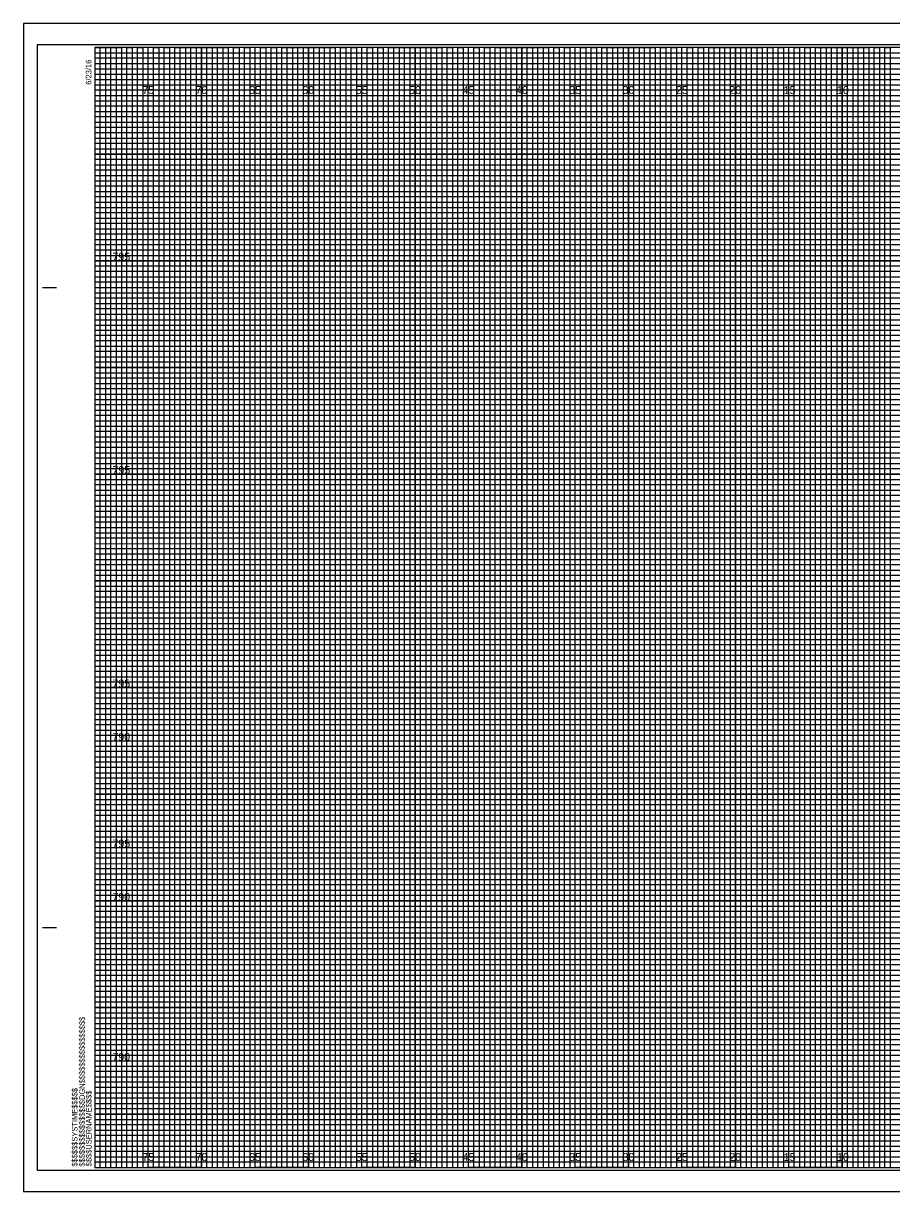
# Model space of a CAD drawing. Extents: x -7 to 162, y -2 to 107.
# Drawn here: x -6.7 to 74.6, y -2.3 to 107.3 of the extents above; entities that cross this region are included whole.
import ezdxf

# ---------------------------------------------------------------- set-up
doc = ezdxf.new("R2010")
doc.units = 0
for name, color, linetype in [('Exist Cross Section Cell', 7, 'Continuous'), ('Exist XS Center Line Elevation Label', 7, 'Continuous'), ('Prop CMT Pvmt Surface Shoulder', 7, 'Continuous'), ('Prop CMT Shld Paved Course 1', 7, 'Continuous'), ('Prop CMT Shld Paved Course 3', 7, 'Continuous'), ('Prop XS Elevation Labels', 7, 'Continuous'), ('Prop XS Finish Grade CurbGutter', 7, 'Continuous'), ('Prop XS Hydro Elevations', 7, 'Continuous'), ('Prop XS SE Text', 7, 'Continuous'), ('Prop XS Side Slope Text', 7, 'Continuous'), ('Sheet DOT Grid CELL', 7, 'Continuous')]:
    doc.layers.add(name, color=color, linetype=linetype)

msp = doc.modelspace()

# ---------------------------------------------------------------- linework, layer by layer
at = {"layer": 'Exist Cross Section Cell'}
for p, q in [((5, 105), (0, 105)), ((5, 0), (5, 105)), ((15, 105), (10, 105)), ((10, 105), (10, 0)), ((15, 0), (15, 105)), ((25, 105), (20, 105)), ((20, 105), (20, 0)), ((25, 0), (25, 105)), ((35, 105), (30, 105)), ((30, 105), (30, 0)), ((35, 0), (35, 105)), ((45, 105), (40, 105)), ((40, 105), (40, 0)), ((45, 0), (45, 105)), ((55, 105), (50, 105)), ((50, 105), (50, 0)), ((55, 0), (55, 105)), ((65, 105), (60, 105)), ((60, 105), (60, 0)), ((65, 0), (65, 105)), ((75, 105), (70, 105)), ((70, 105), (70, 0)), ((10, 0), (5, 0)), ((20, 0), (15, 0)), ((30, 0), (25, 0)), ((40, 0), (35, 0)), ((50, 0), (45, 0)), ((60, 0), (55, 0)), ((70, 0), (65, 0))]:
    msp.add_line(p, q, dxfattribs=at)
for points in [[(0, 100), (160, 100), (160, 95), (0, 95)], [(0, 90), (160, 90), (160, 85), (0, 85)], [(0, 80), (160, 80), (160, 75), (0, 75)], [(0, 70), (160, 70), (160, 65), (0, 65)], [(0, 60), (160, 60), (160, 55), (0, 55)], [(0, 50), (160, 50), (160, 45), (0, 45)], [(0, 40), (160, 40), (160, 35), (0, 35)], [(0, 30), (160, 30), (160, 25), (0, 25)], [(0, 20), (160, 20), (160, 15), (0, 15)], [(0, 10), (160, 10), (160, 5), (0, 5)]]:
    msp.add_lwpolyline(points, dxfattribs=at)
at = {"layer": 'Exist XS Center Line Elevation Label'}
for points in [[(0, 105), (2.5, 105), (2.5, 0), (7.5, 0), (7.5, 105), (12.5, 105), (12.5, 0), (17.5, 0), (17.5, 105), (22.5, 105), (22.5, 0), (27.5, 0), (27.5, 105), (32.5, 105), (32.5, 0), (37.5, 0), (37.5, 105), (42.5, 105), (42.5, 0), (47.5, 0), (47.5, 105), (52.5, 105), (52.5, 0), (57.5, 0), (57.5, 105), (62.5, 105), (62.5, 0), (67.5, 0), (67.5, 105), (72.5, 105), (72.5, 0), (77.5, 0)], [(0, 102.5), (137.5, 102.5)], [(0, 92.5), (160, 92.5), (160, 97.5), (0, 97.5)], [(0, 82.5), (160, 82.5), (160, 87.5), (0, 87.5)], [(0, 72.5), (160, 72.5), (160, 77.5), (0, 77.5)], [(0, 62.5), (160, 62.5), (160, 67.5), (0, 67.5)], [(0, 52.5), (160, 52.5), (160, 57.5), (0, 57.5)], [(0, 42.5), (160, 42.5), (160, 47.5), (0, 47.5)], [(0, 32.5), (160, 32.5), (160, 37.5), (0, 37.5)], [(0, 22.5), (160, 22.5), (160, 27.5), (0, 27.5)], [(0, 12.5), (160, 12.5), (160, 17.5), (0, 17.5)], [(0, 2.5), (160, 2.5), (160, 7.5), (0, 7.5)]]:
    msp.add_lwpolyline(points, dxfattribs=at)
at = {"layer": 'Prop CMT Pvmt Surface Shoulder'}
msp.add_lwpolyline([(-5.4, -0.25), (161.2, -0.25), (161.2, 105.25), (-5.4, 105.25)], close=True, dxfattribs=at)
at = {"layer": 'Prop CMT Shld Paved Course 1'}
for points in [[(0, 0), (0.5, 0), (0.5, 105), (1, 105), (1, 0)], [(1, 0), (1.5, 0), (1.5, 105), (2, 105), (2, 0)], [(2.5, 0), (3, 0), (3, 105), (3.5, 105), (3.5, 0)], [(3.5, 0), (4, 0), (4, 105), (4.5, 105), (4.5, 0)], [(5, 0), (5.5, 0), (5.5, 105), (6, 105), (6, 0)], [(6, 0), (6.5, 0), (6.5, 105), (7, 105), (7, 0)], [(7.5, 0), (8, 0), (8, 105), (8.5, 105), (8.5, 0)], [(8.5, 0), (9, 0), (9, 105), (9.5, 105), (9.5, 0)], [(10, 0), (10.5, 0), (10.5, 105), (11, 105), (11, 0)], [(11, 0), (11.5, 0), (11.5, 105), (12, 105), (12, 0)], [(12.5, 0), (13, 0), (13, 105), (13.5, 105), (13.5, 0)], [(13.5, 0), (14, 0), (14, 105), (14.5, 105), (14.5, 0)], [(15, 0), (15.5, 0), (15.5, 105), (16, 105), (16, 0)], [(16, 0), (16.5, 0), (16.5, 105), (17, 105), (17, 0)], [(17.5, 0), (18, 0), (18, 105), (18.5, 105), (18.5, 0)], [(18.5, 0), (19, 0), (19, 105), (19.5, 105), (19.5, 0)], [(20, 0), (20.5, 0), (20.5, 105), (21, 105), (21, 0)], [(21, 0), (21.5, 0), (21.5, 105), (22, 105), (22, 0)], [(22.5, 0), (23, 0), (23, 105), (23.5, 105), (23.5, 0)], [(23.5, 0), (24, 0), (24, 105), (24.5, 105), (24.5, 0)], [(25, 0), (25.5, 0), (25.5, 105), (26, 105), (26, 0)], [(26, 0), (26.5, 0), (26.5, 105), (27, 105), (27, 0)], [(27.5, 0), (28, 0), (28, 105), (28.5, 105), (28.5, 0)], [(28.5, 0), (29, 0), (29, 105), (29.5, 105), (29.5, 0)], [(30, 0), (30.5, 0), (30.5, 105), (31, 105), (31, 0)], [(31, 0), (31.5, 0), (31.5, 105), (32, 105), (32, 0)], [(32.5, 0), (33, 0), (33, 105), (33.5, 105), (33.5, 0)], [(33.5, 0), (34, 0), (34, 105), (34.5, 105), (34.5, 0)], [(35, 0), (35.5, 0), (35.5, 105), (36, 105), (36, 0)], [(36, 0), (36.5, 0), (36.5, 105), (37, 105), (37, 0)], [(37.5, 0), (38, 0), (38, 105), (38.5, 105), (38.5, 0)], [(38.5, 0), (39, 0), (39, 105), (39.5, 105), (39.5, 0)], [(40, 0), (40.5, 0), (40.5, 105), (41, 105), (41, 0)], [(41, 0), (41.5, 0), (41.5, 105), (42, 105), (42, 0)], [(42.5, 0), (43, 0), (43, 105), (43.5, 105), (43.5, 0)], [(43.5, 0), (44, 0), (44, 105), (44.5, 105), (44.5, 0)], [(45, 0), (45.5, 0), (45.5, 105), (46, 105), (46, 0)], [(46, 0), (46.5, 0), (46.5, 105), (47, 105), (47, 0)], [(47.5, 0), (48, 0), (48, 105), (48.5, 105), (48.5, 0)], [(48.5, 0), (49, 0), (49, 105), (49.5, 105), (49.5, 0)], [(50, 0), (50.5, 0), (50.5, 105), (51, 105), (51, 0)], [(51, 0), (51.5, 0), (51.5, 105), (52, 105), (52, 0)], [(52.5, 0), (53, 0), (53, 105), (53.5, 105), (53.5, 0)], [(53.5, 0), (54, 0), (54, 105), (54.5, 105), (54.5, 0)], [(55, 0), (55.5, 0), (55.5, 105), (56, 105), (56, 0)], [(56, 0), (56.5, 0), (56.5, 105), (57, 105), (57, 0)], [(57.5, 0), (58, 0), (58, 105), (58.5, 105), (58.5, 0)], [(58.5, 0), (59, 0), (59, 105), (59.5, 105), (59.5, 0)], [(60, 0), (60.5, 0), (60.5, 105), (61, 105), (61, 0)], [(61, 0), (61.5, 0), (61.5, 105), (62, 105), (62, 0)], [(62.5, 0), (63, 0), (63, 105), (63.5, 105), (63.5, 0)], [(63.5, 0), (64, 0), (64, 105), (64.5, 105), (64.5, 0)], [(65, 0), (65.5, 0), (65.5, 105), (66, 105), (66, 0)], [(66, 0), (66.5, 0), (66.5, 105), (67, 105), (67, 0)], [(67.5, 0), (68, 0), (68, 105), (68.5, 105), (68.5, 0)], [(68.5, 0), (69, 0), (69, 105), (69.5, 105), (69.5, 0)], [(70, 0), (70.5, 0), (70.5, 105), (71, 105), (71, 0)], [(71, 0), (71.5, 0), (71.5, 105), (72, 105), (72, 0)], [(72.5, 0), (73, 0), (73, 105), (73.5, 105), (73.5, 0)], [(73.5, 0), (74, 0), (74, 105), (74.5, 105), (74.5, 0)]]:
    msp.add_lwpolyline(points, dxfattribs=at)
at = {"layer": 'Prop CMT Shld Paved Course 3'}
msp.add_lwpolyline([(-6.7, -2.25), (161.65, -2.25), (161.65, 107.25), (-6.7, 107.25)], close=True, dxfattribs=at)
at = {"layer": 'Prop XS Finish Grade CurbGutter'}
for p, q in [((161.65, 107.25), (-6.7, 107.25)), ((-6.7, 107.25), (-6.7, -2.25)), ((-6.7, -2.25), (161.65, -2.25))]:
    msp.add_line(p, q, dxfattribs=at)
at = {"layer": 'Prop XS Hydro Elevations'}
for p, q in [((-4.9, 82.5), (-3.65, 82.5)), ((-4.85, 82.5), (-3.6, 82.5)), ((-4.9, 22.5), (-3.65, 22.5)), ((-4.85, 22.5), (-3.6, 22.5)), ((0, 0), (0, 0)), ((0, 0), (0, 0)), ((0, 0), (0, 0)), ((0, 0), (0, 0)), ((0, 0), (0, 0)), ((0, 0), (0, 0)), ((0, 0), (0, 0))]:
    msp.add_line(p, q, dxfattribs=at)
msp.add_lwpolyline([(160, 105), (0, 105), (0, 0), (160, 0)], close=True, dxfattribs=at)
at = {"layer": 'Prop XS Side Slope Text'}
for p, q in [((0, 104.5), (130, 104.5)), ((130, 103.99), (0, 103.99)), ((0, 103.99), (0, 103.5)), ((0, 103.5), (130, 103.5)), ((130, 102.95), (0, 102.95)), ((0, 102.95), (0, 102)), ((0, 102), (160, 102))]:
    msp.add_line(p, q, dxfattribs=at)
for points in [[(0, 101.5), (135, 101.5), (160, 101.5), (160, 101), (0, 101)], [(0, 100.5), (160, 100.5), (160, 99.5), (0, 99.5)], [(0, 99), (160, 99), (160, 98.5), (0, 98.49)], [(0, 98), (160, 98), (160, 97), (0, 97)], [(0, 96.5), (160, 96.5), (160, 96), (0, 96)], [(0, 95.5), (160, 95.5), (160, 94.5), (0, 94.5)], [(0, 94), (160, 94), (160, 93.5), (0, 93.5)], [(0, 93), (160, 93), (160, 92), (0, 92)], [(0, 91.5), (160, 91.5), (160, 91), (0, 91)], [(0, 90.5), (160, 90.5), (160, 89.5), (0, 89.5)], [(0, 89), (160, 89), (160, 88.5), (0, 88.5)], [(0, 88), (160, 88), (160, 86.98), (160, 86.5), (160, 86), (0, 86)], [(0, 87), (160, 87), (160, 86.5), (0, 86.5)], [(0, 85.5), (160, 85.5), (160, 84.5), (0, 84.52)], [(0, 84.52), (160, 84.5), (160, 84), (0, 84)], [(0, 83.5), (160, 83.5), (160, 83), (0, 83)], [(0, 82), (160, 82), (160, 81.5), (0, 81.5)], [(0, 81), (160, 81), (160, 80.5), (0, 80.5)], [(-0.04, 79.45), (160, 79.45), (160, 78.94), (-0.04, 78.94)], [(0, 78.5), (160, 78.5), (160, 78), (0, 78)], [(0, 77), (160, 77), (160, 76.5), (0, 76.5)], [(0, 76), (160, 76), (160, 75.5), (0, 75.5)], [(0, 74.5), (160, 74.5), (160, 74), (0, 74)], [(0, 73.5), (160, 73.5), (160, 73), (0, 73)], [(0, 72), (160, 72), (160, 71.5), (0, 71.5)], [(0, 71), (160, 71), (160, 70.5), (0, 70.5)], [(0, 69.5), (160, 69.5), (160, 68.99), (0, 69)], [(0, 68.5), (160, 68.5), (160, 68), (0, 68)], [(0, 67), (160, 67), (160, 66.5), (0, 66.5)], [(0, 66), (160, 66), (160, 65.5), (0, 65.5)], [(0, 64.5), (160, 64.5), (160, 64), (0, 64)], [(0, 63.5), (160, 63.5), (160, 63), (0, 63)], [(0, 62), (160, 62), (160, 61.5), (0, 61.5)], [(0, 61), (160, 61), (160, 60.5), (0, 60.5)], [(0, 59.5), (160, 59.5), (160, 59), (0, 59)], [(0, 58.5), (160.03, 58.45), (160, 58), (0, 58)], [(0, 57), (160, 57), (160, 56.5), (0, 56.5)], [(0, 56), (160, 56), (160, 55.5), (0, 55.5)], [(0, 54.5), (160, 54.5), (160, 54), (0, 54)], [(0, 53.5), (160, 53.5), (160, 53), (0, 53)], [(0, 52), (160, 52), (160, 51.5), (0, 51.5)], [(0, 51), (160, 51), (160, 50.5), (0, 50.5)], [(0, 49.5), (160, 49.5), (160, 49), (0, 49)], [(0, 48.5), (160, 48.5), (160, 48), (0, 48)], [(0, 47), (160, 47), (160, 46.5), (0, 46.5)], [(0, 46), (160, 46), (160, 45.5), (0, 45.5)], [(0, 44.5), (160, 44.5), (160, 44), (0, 44)], [(0, 43.5), (160, 43.5), (160, 43), (0, 43)], [(0, 42), (160, 42), (160, 41.5), (0, 41.5)], [(0, 41), (160, 41), (160, 40.5), (0, 40.5)], [(0, 39.5), (160, 39.5), (160, 38.99), (0, 39)], [(0, 38.5), (160, 38.5), (160, 38), (0, 38)], [(0, 37), (160, 37), (160, 36.5), (0, 36.5)], [(0, 36), (160, 36), (160, 35.5), (0, 35.5)], [(0, 34.5), (160, 34.5), (160, 34), (0, 34)], [(0, 33.5), (160, 33.5), (160, 33), (0, 33)], [(0, 32), (160, 32), (160, 31.5), (0, 31.5)], [(0, 31), (160, 31), (160, 30.5), (0, 30.5)], [(0, 29.5), (160, 29.5), (160, 29), (0, 29)], [(0, 28.5), (160.03, 28.46), (160, 28), (0, 28)], [(0, 27), (160, 27), (160, 26.5), (0, 26.5)], [(0, 26), (160, 26), (160, 25.5), (0, 25.5)], [(0, 24.5), (160, 24.5), (160, 24), (0, 24)], [(0, 23.5), (160, 23.5), (160, 23), (0, 23)], [(0, 22), (160, 22), (160, 21.5), (0, 21.5)], [(0, 21), (160, 21), (160, 20.5), (0, 20.5)], [(0, 19.5), (160, 19.5), (160, 19), (0, 19)], [(0, 18.5), (160, 18.5), (160, 18), (0, 18)], [(0, 17), (160, 17), (160, 16.5), (0, 16.5)], [(0, 16), (160, 16), (160, 15.5), (0, 15.5)], [(0, 14.5), (160, 14.5), (160, 14), (0, 14)], [(0, 13.5), (160, 13.5), (160, 13), (0, 13)], [(0, 12), (160, 12), (160, 11.5), (0, 11.5)], [(0, 11), (160, 11), (160, 10.5), (0, 10.5)], [(0, 9.5), (160, 9.5), (160, 9), (0, 9)], [(0, 8.5), (160, 8.5), (160, 8), (0, 8)], [(0, 7), (160, 7), (160, 6.5), (0, 6.5)], [(0, 6), (160, 6), (160, 5.5), (0, 5.5)], [(0, 4.5), (160, 4.5), (160, 4), (0, 4)], [(0, 3.5), (160, 3.5), (160, 3), (0, 3)], [(0, 2), (160, 2), (160, 1.5), (0, 1.5)], [(0, 1), (160, 1), (160, 0.5), (0, 0.5)]]:
    msp.add_lwpolyline(points, dxfattribs=at)
at = {"layer": 'Sheet DOT Grid CELL'}
for p, q in [((5, 0), (5, 105)), ((10, 0), (10, 105)), ((15, 0), (15, 105)), ((20, 0), (20, 105)), ((25, 0), (25, 105)), ((30, 0), (30, 105)), ((35, 0), (35, 105)), ((40, 0), (40, 105)), ((45, 0), (45, 105)), ((50, 0), (50, 105)), ((55, 0), (55, 105)), ((60, 0), (60, 105)), ((65, 0), (65, 105)), ((70, 0), (70, 105)), ((0, 100), (160, 100)), ((0, 95), (160, 95)), ((0, 90), (160, 90)), ((0, 85), (160, 85)), ((0, 80), (160, 80)), ((0, 75), (160, 75)), ((0, 70), (160, 70)), ((0, 65), (160, 65)), ((0, 60), (160, 60)), ((0, 55), (160, 55)), ((0, 50), (160, 50)), ((0, 45), (160, 45)), ((0, 40), (160, 40)), ((0, 35), (160, 35)), ((0, 30), (160, 30)), ((0, 25), (160, 25)), ((0, 20), (160, 20)), ((0, 15), (160, 15)), ((0, 10), (160, 10)), ((0, 5), (160, 5))]:
    msp.add_line(p, q, dxfattribs=at)

# ---------------------------------------------------------------- texts
at = {"layer": 'Prop XS Elevation Labels'}
for s, p in [('795', (1.64, 85)), ('795', (1.64, 65)), ('795', (1.64, 45)), ('790', (1.63, 40)), ('795', (1.64, 30)), ('790', (1.63, 25)), ('790', (1.63, 10))]:
    msp.add_text(s, height=0.75, dxfattribs=at).set_placement(p)
at = {"layer": 'Prop XS Hydro Elevations'}
for s, p in [('6/23/16', (-0.33, 101.5)), ('$$$$$$$$$$$$$$$$DGN$$$$$$$$$$$$$$$$', (-0.94, 0.09)), ('$$$$$$SYSTIME$$$$$', (-1.63, 0.09)), ('$$$$USERNAME$$$$', (-0.31, 0.12))]:
    msp.add_text(s, height=0.525, rotation=90, dxfattribs=at).set_placement(p)
at = {"layer": 'Prop XS SE Text'}
for s, p in [('75', (4.44, 100.62)), ('70', (9.43, 100.62)), ('65', (14.44, 100.62)), ('60', (19.43, 100.62)), ('55', (24.44, 100.62)), ('50', (29.43, 100.62)), ('45', (34.44, 100.62)), ('40', (39.43, 100.62)), ('35', (44.44, 100.62)), ('30', (49.43, 100.62)), ('25', (54.44, 100.62)), ('20', (59.43, 100.62)), ('15', (64.53, 100.62)), ('10', (69.52, 100.62)), ('75', (4.44, 0.62)), ('70', (9.43, 0.62)), ('65', (14.44, 0.62)), ('60', (19.43, 0.62)), ('55', (24.44, 0.62)), ('50', (29.43, 0.62)), ('45', (34.44, 0.62)), ('40', (39.43, 0.62)), ('35', (44.44, 0.62)), ('30', (49.43, 0.62)), ('25', (54.44, 0.62)), ('20', (59.43, 0.62)), ('15', (64.53, 0.62)), ('10', (69.52, 0.62))]:
    msp.add_text(s, height=0.75, dxfattribs=at).set_placement(p)

doc.saveas('drawing.dxf')
